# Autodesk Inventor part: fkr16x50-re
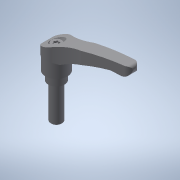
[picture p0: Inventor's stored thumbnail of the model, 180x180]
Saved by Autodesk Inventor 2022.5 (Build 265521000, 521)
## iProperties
Created: 2017-09
Part Number: fkr16x50-re
Material: 一般
Document SubType Name: Modeling
Designer: imaocorp
Density: 1 g/cm^3
Appearance: 既定
Author: imaocorp
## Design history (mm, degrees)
node "fkr16x50-re.x_t1"
node "fkr16x50-re"
node "Base1"
